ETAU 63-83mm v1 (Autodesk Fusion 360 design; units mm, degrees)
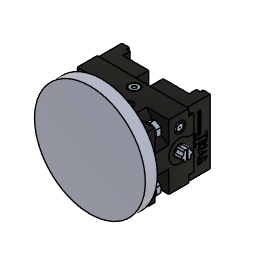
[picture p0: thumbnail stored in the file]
parameter "Ouverture" = 80
base_feature "Base Feature1"
joint_origin "JointOrigin1" OffsetX 0 OffsetY 0 OffsetZ 0
base_feature "Base Feature1"
joint_origin "JointOrigin1" OffsetX 0 OffsetY 0 OffsetZ 0
joint_origin "JointOrigin2" OffsetX 0 OffsetY 0 OffsetZ 0
base_feature "Base Feature1"
joint "Assemble1" alignOffsetX 0 alignOffsetY 0 alignOffsetZ 7.8 (= "Ouverture / 2 - 32.2 mm")
joint "Assemble2" alignOffsetX 0 alignOffsetY 0 alignOffsetZ -7.8 (= "-Ouverture / 2 + 32.2 mm")
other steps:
create_component "CreateComponent1"
create_component "CreateComponent2"
create_component "CreateComponent3"
joint_origin "JointOrigin2" OffsetX 0 OffsetY 0 OffsetZ 0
